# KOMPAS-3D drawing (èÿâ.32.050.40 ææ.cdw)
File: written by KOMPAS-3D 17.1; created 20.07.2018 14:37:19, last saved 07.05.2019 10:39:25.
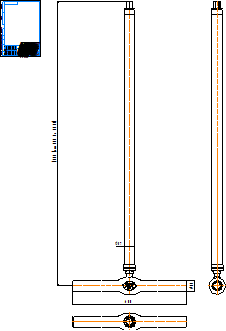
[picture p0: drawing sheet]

Sheet 1: A4, portrait

Title block, sheet 1: name: КШГ.32.050.40 СС; material: Внимание! Данный продукт является объектом авторского права ООО «Торговый Дом АДЛ». / Запрещается изменение, копирование, распространение / (в том числе путем копирования на другие сайты и ресурсы в Интернете) / или любое иное использование информации и объектов без предварительного / согласия правообладателя (ООО «Торговый Дом АДЛ»).; sheets: 1; organisation: ООО "Торговый дом АДЛ"; sheet format: A4; stored path: C:\Users\tra\Desktop\2д чертежи\Шаровые краны БИВАЛ\КШ_Бивал_серия_32\KOMPAS 2D\КШГ.32.050.40 СС.cdw

Views: Вид 1, Проекционный вид 2, Проекционный вид 3
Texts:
  kka
  adl
  (от 250 до 5000)
Dimensions and other numbers on the sheet: 600; 57; 1500; 1:1; 1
